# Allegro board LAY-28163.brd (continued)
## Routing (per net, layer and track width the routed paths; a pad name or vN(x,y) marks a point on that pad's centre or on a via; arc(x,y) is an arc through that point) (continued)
P3V3_K64F: length 34.4
  TOP w0.254: U14.40 54.33,12.98 C46.1 ; C49.1 57.42,10.41 U14.48
  TOP w0.305: C42.1 70.72,18.17 70.63,18.17 U14.75 ; U14.8 55.67,28.18 C25.1 ; U14.89 66.04,26.8 66.04,27.19 v1(66.33,27.48) ; U14.61 65.62,13.29 66.05,13.29 v1(66.07,13.27)
  TOP w0.33: v1(50.61,23.46) 50.61,23.34 U14.22
  TOP w0.381: C27.1 v1(66.33,27.48)
  TOP w0.508: C47.1 v1(67.39,12.41)
  TOP w0.635: 38.47,12.94 J20.2 39.42,13.89 ; v1(54.82,29.68) 55.18,29.68 C25.1 ; C49.1 57.01,9.99 v1(57.55,9.45) ; 42.42,13.76 R64.2 41.91,14.27 ; R52.1 v1(46.61,24.64) ; R66.2 41.75,13.88 ; R66.2 40.98,13.25 ; R66.2 40.22,13.88 ; C42.1 v1(72.12,17.57) ; C46.1 v1(52.74,12.06) ; R54.1 49.15,24.17 C37.1 50.61,23.75 v1(50.61,23.46)
  BOTTOM w0.635: 41.96,30.63 J9.1 ; J9.1 42.63,30.63 ; J9.1 42.63,31.3 ; J20.2 39.2,13.15 ; J20.2 38.47,12.94 ; J20.2 39.2,14.63 ; J20.2 39.42,13.89 ; 47.96,10.42 J23.2 47.75,9.68
  vias: v1(39.82,13.21) v1(39.83,12.04) v1(41.02,12.07) v1(41.56,13.1) v1(42.45,13.15) v1(42.48,12.12)
P3V3_SDA: length 48.2
  TOP w0.203: v1(42.56,42.75) 42.16,43.15 U3.1
  TOP w0.254: R4.2 v1(40.95,44.92) ; U2.1 46.72,43.77 v1(46.59,43.64) ; U5.7 19.63,39.65 19.32,39.34 19.32,38.97 19.09,38.73 18.74,38.73 C12.1 18.52,38.51 C15.1 ; v1(45.45,42.33) 45.88,41.91 U7.1 ; v1(36.39,35.29) U10.7 ; U5.11 v1(22.19,39.43) ; U9.5 v1(41.7,39.75) ; U12.1 v1(46.09,35.35)
  TOP w0.305: U5.1 v1(17.06,42.22)
  TOP w0.381: v1(36.39,35.29) 36.39,34.51 36.87,34.03 C17.1 ; J18.1 26.43,20.22 26.17,19.97 R61.2 ; v1(41.6,41.13) R14.1 ; R26.1 v1(40.64,39.36) ; v1(47.23,35.41) 47.64,34.99 R37.1 ; R23.1 v1(47.69,37.62)
  TOP w0.508: v1(42.97,39.01) 42.99,39.01 43.32,39.34 R27.2 ; v1(43.81,43.76) R12.1 ; R14.1 C8.1
  TOP w0.635: R17.1 v1(10.45,41.1) ; J10.1 27.32,31.3 C18.1 ; v1(20.26,36.77) C15.1 ; R21.1 v1(26.1,38.4) ; v1(15.19,42.15) C10.1 ; R35.1 v1(28.45,35.22)
  BOTTOM w0.635: J7.1 9.23,39.79 ; J7.1 8.28,38.83 ; J7.1 9.23,37.88 ; J10.1 27.02,31.3 ; 33.04,34.06 33.04,29.56 31.9,28.42 30.46,28.42 26.65,24.61 26.65,21.08 J18.1
P3V3_VREG: length 18.1
  TOP w0.762: 34.95,12.97 J19.2 34.22,13.18 ; C51.1 34.2,8.95 ; C51.1 34.2,7.42 ; C51.1 33.57,7.42 ; C51.1 33.57,8.18 ; 30.31,13.2 U17.2 29.61,13.2 ; 27.55,8.3 U17.4 ; U17.4 29.61,7 ; U17.4 29.61,9.59 ; U17.4 31.67,8.3 ; 34.28,9.95 D11.A ; D11.A 33.7,9.95 ; D11.A 33.64,10.84 ; D11.A 34.28,11.73
P5V0_SDA_USB_CONN_VBUS: length 5.8
  TOP w0.406: J26.1 5.21,43.49 6.51,44.79 U1.1
  TOP w0.762: U1.1 L1.1
P5V0_USB_CONN_VBUS: length 6
  TOP w0.406: U15.1 6.53,13.92 5.27,12.65 J22.1
  TOP w0.635: L5.1 8.84,14.59 8.16,13.92 U15.1
P5V_K64_USB: length 37.5
  TOP w0.508: J21.2 13.3,13.86 ; J21.2 13.3,11.95 ; J21.2 14.25,12.9 ; J21.2 12.35,12.9 ; C45.1 11.46,13.46 ; C45.1 10.95,12.95 ; C45.1 10.95,13.97 ; L5.2 10.24,15.72 ; L5.2 10.73,15.12 ; L5.2 10.24,14.52 ; 19.01,11.97 D8.A ; D8.A 18.12,12.62 ; D8.A 19.9,12.62 ; 15.3,12.62 D7.A ; D7.A 16.19,13.27 ; D7.A 16.19,11.97 ; D7.A 17.08,12.62
  BOTTOM w0.762: J16.2 40.24,19.65 37.63,19.65 35.93,17.95 33.94,17.95 29.76,13.76 21.38,13.76 v2(18.97,11.36)
P5V_OPT_VR: length 4.5
  TOP w0.762: J27.3 4.49,4.52 4.88,4.9 C53.1
  TOP w0.889: C53.1 D13.A
P5V_SDA: length 68.3
  TOP w0.127: v1(18.81,39.35) 18.8,39.36 18.8,39.54 U5.6
  TOP w0.381: R5.1 v1(23.71,45.86)
  TOP w0.508: v2(29.35,39.98) 29.35,39.22 30.97,37.6 35.03,37.6 35.63,37.01 R34.1 35.6,35.87 34.67,34.94 C16.1 ; C16.1 34.67,32.58 C19.1 ; C16.1 33.29,34.33 U11.1 ; R8.1 v1(17.91,45.84)
  TOP w0.635: v2(12.2,46.18) 12.1,46.18 12.09,46.19 C1.1 L1.2
  BOTTOM w0.381: v1(23.71,45.86) 23.13,46.44 19.09,46.44 18.48,45.84 v1(17.91,45.84)
  BOTTOM w0.508: v1(17.91,45.84) 17.28,45.84 16.28,44.84 13.54,44.84 v2(12.2,46.18) ; v1(23.71,45.86) 24.91,44.66 28.25,44.66 29.8,43.11 29.8,41.2 29.35,40.75 v2(29.35,39.98)
  BOTTOM w0.762: v1(18.81,39.35) 18.81,37.39 17.8,36.38 13.87,36.38 13.33,36.92 8.25,36.92 7.38,37.79 7.38,42.26 11.31,46.18 v2(12.2,46.18)
P5V_SDA_PSW: length 23.2
  TOP w0.635: U11.6 v2(29.61,34.34)
  TOP w0.762: D6.A 21.74,20.49 v2(20.39,20.49) D5.A
  BOTTOM w0.635: v2(29.61,34.34) 29.61,32.3 27.43,30.12 24.69,30.12 20.39,25.82 v2(20.39,20.49)
P5V_USB: length 53.3
  TOP w1.016: D5.C 17.01,17.94 v2(16.19,17.12) D7.C 14.93,15.17 14.65,15.44 J21.1 ; D13.C v2(8.76,7.28)
  INT_1 w1.016: v2(15.86,6.86) 16.49,6.23 16.98,6.23 19.69,3.53 22.53,3.53 25.14,0.93 36.94,0.93 38.06,2.05 J3.10
  BOTTOM w1.016: v2(8.76,7.28) 9.65,7.28 10.07,6.86 v2(15.86,6.86) 16.82,7.82 16.82,16.49 v2(16.19,17.12)
VBAT: length 6.7
  TOP w0.254: C43.1 51.06,15.06 51.06,16.77 U14.30
  TOP w0.635: J23.1 50.5,14.35 C43.1
VDDA_ENET: length 18.8
  TOP w0.254: C24.1 32.38,29.47 U13.2
  TOP w0.508: L3.2 30.29,31.08 30.29,30.25 v1(30.15,30.11) ; L3.2 31.66,31.09 C21.1 32.87,31.09 C22.1 C24.1 ; L3.2 R42.2 ; v1(21.76,32.28) 20.78,32.28 R41.1
  INT_1 w0.254: v1(30.15,30.11) 29.29,30.97 28.11,30.97 27.35,30.2 23.84,30.2 v1(21.76,32.28)
VDDIO_ENET: length 70.1
  TOP w0.279: U13.14 30.88,23.72 C39.1 30.88,21.27 30.88,21.27 J17.1
  TOP w0.381: D3.1 v1(40.72,26.92)
  TOP w0.635: J17.1 29.67,20.24 28.78,21.13 R55.1 28.77,22.63 R56.1 ; v1(38.17,24.86) 38.17,25.35 R50.1 ; R60.2 v1(33.3,21.3) ; R76.1 v1(11.05,16.7)
  BOTTOM w0.635: J13.13 2.73,26.93 5.57,24.09 8.02,24.09 11.05,21.06 v1(11.05,16.7) 11.75,16.7 13.2,18.15 18.06,18.15 19.99,16.22 28.41,16.22 29.04,16.86 29.04,18.4 J17.1 31.94,21.3 v1(33.3,21.3) 35.52,21.3 38.17,23.94 v1(38.17,24.86) 38.17,26.36 38.73,26.92 v1(40.72,26.92)
VDDPLL_1.2V: length 3.2
  TOP w0.114: U13.1 34.42,28.34 C26.1 36.08,28.34 C28.1
ADC0_DM0/ADC1_DM3: length 45.7
  TOP w0.114: v1(51.23,24.6) 51.64,24.6 51.73,24.51 51.73,24.35 U14.19
  INT_1 w0.119: J2.7 35.11,48.29 35.23,48.17 35.23,47.38 37.12,45.49 37.12,41.16 39.72,38.56 39.72,36.24 39.38,35.9 39.38,30.26 40.98,28.65 49.36,28.65 51.71,31 52.8,31 53.3,30.5 53.3,28.18 50.98,25.85 50.98,25.24 51.23,24.99 v1(51.23,24.6)
ADC0_DM1: length 30.5
  TOP w0.114: v1(56.74,23.83) 55.08,23.83 U14.15
  INT_1 w0.13: v1(56.74,23.83) 56.74,18.69 62.49,12.94 62.49,10.2 58.94,6.65 54.91,6.65 J4.3
ADC0_DP0/AD1_DP3: length 45.4
  TOP w0.114: v1(51.83,25.2) 51.83,24.81 51.94,24.7 52.08,24.7 U14.18
  INT_1 w0.119: J2.5 35.65,48.29 35.53,48.17 35.53,47.51 37.42,45.62 37.42,41.28 40.02,38.69 40.02,36.12 39.67,35.78 39.67,30.38 41.11,28.95 49.24,28.95 51.59,31.3 52.92,31.3 53.6,30.62 53.6,28.05 51.27,25.73 51.27,25.37 51.44,25.2 v1(51.83,25.2)
ADC0_DP1: length 31.9
  TOP w0.114: 54.3,25.31 55.2,24.41 v1(56.15,24.41)
  INT_1 w0.13: v1(56.15,24.41) 56.15,18.62 61.92,12.85 61.92,10.43 58.55,7.06 52.78,7.06 J4.1
ADC1_DM0/ADC0_DM3: length 52
  TOP w0.114: v1(43.52,22.07) 43.93,22.07 44.05,22.2 44.05,24.2 42.68,25.58 42.68,26.54 42.6,26.63 v1(42.19,26.63) ; v1(47.26,20.98) 47.55,20.69 48.61,20.69 49,20.3 51.18,20.3 52.64,21.76 52.64,22.02 U14.21
  INT_1 w0.119: v1(47.26,20.98) 46.98,20.7 46.79,20.7 44.96,22.52 44.36,22.52 44.19,22.35 43.8,22.35 v1(43.52,22.07) ; J2.13 27.58,48.29 28.61,47.26 29.99,47.26 30.06,47.32 30.56,47.32 31.21,46.67 32.84,46.67 34.53,44.98 34.53,43.19 36.14,41.59 36.14,40.34 38.2,38.27 38.2,34.66 38.2,32.72 37.7,32.22 37.7,28.03 38.37,27.36 41.85,27.36 42.19,27.02 v1(42.19,26.63)
ADC1_DM1: length 28.1
  TOP w0.114: v1(58.18,22.76) 54.73,22.76 U14.17
  INT_1 w0.13: J4.7 59.49,5.12 63.55,9.18 63.55,13.24 58.18,18.61 v1(58.18,22.76)
ADC1_DP0/ADC0_DP3: length 51.8
  TOP w0.114: U14.20 52.92,22.45 52.92,21.65 51.3,20.03 48.88,20.03 48.5,20.41 47.55,20.41 v1(47.26,20.12) ; v1(44.12,21.46) 44.12,21.88 44.33,22.08 44.33,24.32 44,24.65 44,24.79 44.17,24.96 44.17,25.1 44.07,25.2 43.92,25.2 43.75,25.03 43.61,25.03 43.51,25.13 43.51,25.28 43.68,25.45 43.68,25.59 43.58,25.69 43.44,25.69 43.27,25.52 43.13,25.52 42.96,25.69 42.96,26.66 42.8,26.82 v1(42.8,27.24)
  INT_1 w0.119: v1(42.8,27.24) 42.4,27.24 41.97,27.66 38.49,27.66 38,28.15 38,32.09 38.5,32.59 38.5,34.17 38.5,34.17 38.5,34.79 38.5,34.79 38.5,38.4 36.43,40.46 36.43,41.76 34.83,43.36 34.83,45.1 32.96,46.97 31.33,46.97 30.68,47.62 30.35,47.62 29.68,48.29 J2.11 ; v1(47.26,20.12) 46.98,20.4 46.67,20.4 44.84,22.23 44.49,22.23 44.4,22.14 44.4,21.75 v1(44.12,21.46)
ADC1_DP1: length 29.1
  TOP w0.114: U14.16 54.91,23.29 v1(57.39,23.29)
  INT_1 w0.13: v1(57.39,23.29) 57.39,18.64 63.02,13 63.02,9.93 59.34,6.25 57.05,6.25 J4.5
ADC1_SE18: length 51.6
  TOP w0.114: v1(39.1,26.22) 39.41,25.91 39.42,25.91 41.41,23.91 v1(41.41,21.33) ; v1(48.51,19.67) 48.94,19.24 50.11,19.24 U14.26
  INT_1 w0.13: v1(39.1,26.22) 38.64,26.22 36.55,28.3 36.55,30.1 37.24,30.79 37.24,38.57 35.78,40.03 35.78,41.45 34.54,42.69 33.25,42.69 32.57,43.37 32.57,45.35 31.74,46.17 30.69,46.17 29.86,47 22.7,47 J2.17 ; v1(48.51,19.67) 46.84,19.67 45.62,20.9 41.84,20.9 v1(41.41,21.33)
AREF: length 42.7
  TOP w0.114: R53.2 45.96,25.12 45.96,25.25 45.29,25.92 45.29,27.55 v1(44.71,28.14)
  INT_1 w0.13: v1(44.71,28.14) 43.24,28.14 43.03,28.34 40.1,28.34 39.04,29.41 39.04,36.15 39.43,36.54 39.43,38.2 36.78,40.85 36.78,41.96 35.16,43.58 35.16,45.5 32.96,47.7 32.96,48.66 32.09,49.53 25.25,49.53 J2.16
CPU_PER_1_RST_B: length 6.9
  TOP w0.114: J14.1 43,24.49 41.74,25.75 R47.1 R45.2
CRS_DV: length 6.3
  TOP w0.114: RN1.1 35.47,22.08 35.47,22.08 v1(34.92,22.08) ; U13.15 31.38,23.61 v1(31.54,23.44)
  INT_1 w0.13: v1(34.92,22.08) 33.56,23.44 v1(31.54,23.44)
DAC0_OUT: length 28.5
  TOP w0.114: U14.27 54.09,21.93 v1(58.67,21.93)
  INT_1 w0.13: v1(58.67,21.93) 58.67,18.66 64.04,13.29 64.04,8.13 63.54,7.64 J4.11
DC_JACK: length 2.9
  TOP w1.016: J24.1 21.39,11.12 21.76,11.49 21.76,11.52 21.77,11.52 D9.A
ENET1_CT: length 19
  TOP w0.508: v1(17.75,33.3) C20.1 R41.2
  INT_1 w0.508: v1(17.75,33.3) 12.17,33.3 11.13,32.26 11.13,30.03 J13.3
  BOTTOM w0.127: J13.6 13.62,26.27 13.62,27.54 J13.3
ENET1_RX+: length 25.9
  TOP w0.089: v1(22.34,23.62) 22.08,23.36 19.73,23.36 19.07,24.02 R51.1 18.48,24.14 18.39,24.05 18.39,23.47 18.3,23.38 16.98,23.38 16.67,23.7 13.99,23.7 13.37,23.08 13,23.08 J13.7 ; U13.4 31.38,28.84 31.5,28.96 31.5,29.57 v1(31.22,29.86)
  INT_1 w0.089: v1(31.22,29.86) 31.45,29.62 31.45,28.91 31.17,28.63 30.59,28.63 25.33,23.37 22.6,23.37 v1(22.34,23.62)
ENET1_RX-: length 26.5
  TOP w0.089: v1(22.34,22.8) 22.04,23.11 19.73,23.11 19.07,22.45 R59.1 18.48,22.36 18.39,22.45 18.39,23.04 18.3,23.12 16.88,23.12 16.56,23.44 14.1,23.44 13.81,23.16 13.81,22.59 14.03,22.36 J13.8 ; U13.3 31.88,28.84 31.76,28.96 31.76,29.57 v1(32.04,29.86)
  INT_1 w0.089: v1(32.04,29.86) 31.71,29.53 31.71,28.8 31.28,28.37 30.7,28.37 25.44,23.11 22.65,23.11 v1(22.34,22.8)
ENET1_TX+: length 22.3
  TOP w0.089: J13.1 13.52,30.71 13.56,30.6 13.45,30.44 13.45,29.08 14,28.52 17.2,28.52 17.87,29.19 18.24,29.19 18.33,29.1 18.33,28.53 18.42,28.44 R48.1 19.01,28.5 19.7,29.2 21.63,29.2 22.01,29.59 28.14,29.59 28.4,29.33 29.98,29.33 30.38,28.93 U13.6
ENET1_TX-: length 22.3
  TOP w0.089: J13.2 13.91,30.52 13.79,30.48 13.7,30.36 13.7,29.18 14.11,28.78 17.09,28.78 17.76,29.45 18.24,29.45 18.33,29.54 18.33,30.11 18.42,30.2 R44.1 19.01,30.14 19.7,29.45 21.52,29.45 21.91,29.84 28.25,29.84 28.5,29.58 30.09,29.58 30.88,28.79 U13.5
ENET_1_RX_RDIV: length 5.3
  TOP w0.114: C36.1 20.59,25.14 20.59,25.13 R51.2 v1(21.48,24.14) ; v1(21.48,22.16) 21.28,22.36 R59.2
  INT_1 w0.13: v1(21.48,24.14) 21.48,22.62 21.48,22.61 v1(21.48,22.16)
ENET_1_TX_RDIV: length 5.1
  TOP w0.114: C31.1 20.53,27.68 20.53,27.69 R48.2 20.54,28.45 v1(21.5,28.45) ; R44.2 v1(21.5,30.2)
  INT_1 w0.13: v1(21.5,30.2) v1(21.5,28.45)
EXTAL32_RTC: length 2.6
  TOP w0.114: U14.29 50.63,17.05 50.63,16.27 R63.1
EXTAL_32.768KHZ: length 5.2
  TOP w0.114: Y3.2 47.38,12.28 47.81,12.28 C48.1 48.52,12.99 48.52,13.47 48.49,13.5 48.49,14.13 49.13,14.77 R63.2
FXOS8700CQ_CRST: length 3.7
  TOP w0.114: v1(52.26,38.29) 51.82,37.85 C13.1
  TOP w0.127: v1(52.26,38.29) 52.7,38.29 52.79,38.38 U8.8
FXOS8700CQ_I2C_SA0: length 7.1
  TOP w0.114: v1(51.24,38.88) 50.83,38.88 50.79,38.92 TP8.1 R32.2 R31.1
  TOP w0.127: U8.7 v1(51.24,38.88)
FXOS8700CQ_I2C_SA1: length 7.8
  TOP w0.114: R40.2 R43.1 57.09,32.17 TP11.1 56.16,33.11 56.16,33.41 v1(55.82,33.74)
  TOP w0.127: v1(55.82,33.74) 55.82,34.63 55.82,34.63 55.82,35 55.82,35.01 U8.10
I2S_MCLK: length 8.6
  TOP w0.114: J1.7 57.16,47.02 61.14,47.02 62.77,45.39 R79.1
K64_MICRO_USB_DN: length 2.7
  TOP w0.114: U14.11 54.56,27.17 54.56,27.33 54.48,27.41 54.47,27.41 54.14,27.75 R49.2
K64_MICRO_USB_DP: length 2.7
  TOP w0.114: R46.2 54.33,27.95 54.59,27.69 54.59,27.69 54.75,27.53 54.91,27.53 U14.10
LED1/SPEED: length 18.8
  TOP w0.114: v1(34.37,27.13) 34.37,27.13 U13.23 ; v1(22.54,34.11) R36.1
  INT_1 w0.13: v1(34.37,27.13) 34.37,27.63 32.92,29.08 32.92,29.75 32.02,30.65 31.99,30.65 31.14,31.5 27.9,31.5 27.02,30.62 24.72,30.62 22.54,32.8 v1(22.54,34.11)
LED2_LINK: length 7.8
  TOP w0.635: R76.2 7.98,16.7 v1(7.93,16.75)
  BOTTOM w0.635: v1(7.93,16.75) 6.7,16.75 3.78,19.67 3.53,19.67 J13.11
LEDRGB_BLUE: length 5.7
  TOP w0.114: R71.1 v1(73.43,10.26) TP14.1 76.3,10.26 76.85,9.71 D12.3
LEDRGB_GREEN: length 7.6
  TOP w0.114: R73.1 v1(73.47,8.77) TP17.1 75.62,7.54 78.05,7.54 78.35,7.84 D12.4
LEDRGB_RED: length 7.5
  TOP w0.114: D12.1 78.35,12.71 78.07,12.99 75.57,12.99 TP13.1 v1(73.39,11.81) R68.2
LVLRST_EN: length 1.1
  TOP w0.114: R4.1 41.97,45.25 41.98,45.24 U3.5
MIC2005_CSLEW: length 4.2
  TOP w0.114: U11.5 31.58,35.29 32.17,34.7 32.17,33.56 C19.2
MMA8451_BYP: length 6
  TOP w0.114: C3.1 56.09,45.02 56.26,44.85 TP4.1 v1(56.82,43.99)
  TOP w0.127: U8.2 56.82,42.72 56.83,42.73 56.83,43.14 56.82,43.14 56.82,43.32 56.82,43.52 56.82,43.52 v1(56.82,43.99)
NC1: length 3.1
  TOP w0.114: J13.4 13.72,26.17 J13.5
Net_211: length 3.5
  TOP w0.127: 57.6,38.88 v1(61.06,38.88)
P5-9V_VIN: length 54
  TOP w0.889: J27.1 10.69,4.05 10.69,4.82 10.67,4.84 C54.1 C52.1 C50.1 v1(10.67,10.51)
  TOP w1.016: D10.A v2(24.67,11.2)
  INT_1 w0.889: v2(24.67,11.2) 23.05,12.82 18.63,12.82 16.21,10.4 10.78,10.4 v1(10.67,10.51)
  BOTTOM w0.889: J3.16 47.31,4.21 47.31,5.81 45.63,7.5 28.37,7.5 v2(24.67,11.2)
P5-9V_VIN_VR: length 17.3
  TOP w0.508: C41.1 24.74,17.34 ; C41.1 23.21,17.34 ; C41.1 23.97,16.71 ; D9.C 22.66,15.17 ; D9.C 21.77,13.87 ; D9.C 20.88,15.17 ; 22.64,17.93 D6.C 20.86,17.93 ; 27.31,13.2 U17.3 ; U17.3 28.1,14.5 ; U17.3 26.52,14.5 ; 23.78,15.17 D10.C ; D10.C 24.67,16.46 ; D10.C 25.56,15.17 ; D10.C 24.67,13.87 ; 19.01,13.87 D8.C ; D8.C 19.9,15.17 ; D8.C 18.12,15.17
  vias: v1(25.97,14.85)
PHY_RST_B: length 1.2
  TOP w0.114: D3.2 40.72,27.97 40.73,27.98 40.73,28.78
POWER_EN: length 16
  TOP w0.114: R29.1 27.79,39.2 27.27,38.68 v1(27.27,37.98) ; 17.86,43.05 v1(16.94,43.97)
  INT_1 w0.13: v1(27.27,37.98) 26.29,38.96 21.95,38.96 v1(16.94,43.97)
PTA0: length 40.8
  TOP w0.114: v1(54.81,17.7) U14.34 ; v1(49.08,24.99) 49.08,29.24 48.91,29.41 J11.1
  INT_1 w0.13: v1(49.08,24.99) 49.08,24.55 50.14,23.48 50.14,22.36 v1(54.81,17.7) ; J2.2 42.81,49.74 42.81,46.78 47.13,42.47 47.13,36.29 47.82,35.6 47.82,32.86 48.91,31.77 J11.1
PTA1: length 42.1
  TOP w0.114: v1(60.43,21.24) 59.64,20.45 58.27,20.45 U14.35
  INT_1 w0.13: v1(60.43,21.24) 60.43,22.32 57.97,24.78 57.97,32.42 58.5,32.95 58.5,43.9 54.62,47.78 54.62,49.54 J1.8
PTA2: length 41.7
  TOP w0.114: R80.2 54.17,31.58 v1(54.18,31.59) ; U14.36 v1(55.98,17.45)
  INT_1 w0.13: v1(55.98,17.45) 54.96,18.48 54.96,19.55 54.61,19.91 54.61,27.62 55.32,28.33 55.32,30.46 v1(54.18,31.59) 55.12,32.53 55.12,33.61 54.83,33.91 54.83,41.9 49.55,47.18 49.55,49.55 J1.12
PTA3: length 24.8
  TOP w0.114: J9.2 41.55,30.44 42.37,30.44 44.01,28.8 J12.2 44.01,26.06 45.01,25.06 v1(45.01,23.51) ; 54.3,15.06 v1(55.28,16.04)
  INT_1 w0.13: v1(55.28,16.04) 52.98,16.04 45.51,23.51 v1(45.01,23.51)
PTA4: length 34.4
  TOP w0.114: v1(66.63,10.01) 69.22,7.43 C55.1 R75.2 72.79,4.53 72.8,4.53 SW3.1 ; U14.38 59.43,19.48 v1(59.88,19.48)
  INT_1 w0.13: v1(66.63,10.01) 68.7,12.08 68.7,13.69 67.63,14.77 63.91,14.77 59.88,18.8 v1(59.88,19.48)
PTA5: length 39
  TOP w0.114: RN1.7 v1(38.76,21.21) ; v1(55.89,15.24) U14.39
  INT_1 w0.13: v1(38.76,21.21) 39.39,20.58 39.39,19.47 40,18.86 43.91,18.86 44.02,18.98 44.02,20.2 44.14,20.31 44.3,20.31 44.41,20.2 44.41,18.97 44.53,18.85 44.69,18.85 44.8,18.97 44.8,20.2 44.92,20.31 45.08,20.31 45.19,20.2 45.19,19.03 45.3,18.92 46.69,18.92 46.8,19.03 46.8,19.14 46.92,19.26 47.08,19.26 47.19,19.14 47.19,19.03 47.31,18.92 47.47,18.92 47.58,19.03 47.58,19.14 47.69,19.26 47.86,19.26 47.97,19.14 47.97,19.03 48.08,18.92 48.87,18.92 49.05,18.74 49.05,18.58 48.5,18.03 48.5,17.87 48.62,17.75 48.78,17.75 49.33,18.3 49.49,18.3 49.8,17.99 49.8,17.83 49.28,17.31 49.28,17.15 49.39,17.04 49.55,17.04 50.07,17.56 50.23,17.56 50.87,16.92 50.87,16.76 50.36,16.25 50.36,16.09 50.47,15.97 50.63,15.97 51.15,16.48 51.31,16.48 51.42,16.37 51.42,16.21 50.91,15.7 50.91,15.54 51.02,15.42 51.18,15.42 51.7,15.94 51.86,15.94 52.23,15.56 52.95,15.56 53.07,15.45 53.07,14.9 53.18,14.79 53.34,14.79 53.45,14.9 53.45,15.45 53.57,15.56 53.73,15.56 53.84,15.45 53.84,14.9 53.96,14.79 54.12,14.79 54.23,14.9 54.23,15.45 54.35,15.56 54.51,15.56 54.62,15.45 54.62,14.9 54.73,14.79 54.9,14.79 55.01,14.9 55.01,15.45 55.12,15.56 55.58,15.56 v1(55.89,15.24)
PTA12: length 40.4
  TOP w0.114: v1(57.52,14.95) 57.21,14.64 57.21,14.45 56.98,14.22 56.98,14.21 55.24,12.47 54.6,12.47 ; v1(38.76,20.41) RN1.6
  INT_1 w0.13: v1(57.52,14.95) 57.21,14.64 57.21,14.45 56.68,13.92 56.17,13.92 56.06,14.03 56.06,14.31 55.94,14.42 55.78,14.42 55.67,14.31 55.67,14.03 55.55,13.92 55.39,13.92 55.28,14.03 55.28,14.31 55.16,14.42 55,14.42 54.89,14.31 54.89,14.03 54.78,13.92 54.61,13.92 54.5,14.03 54.5,14.31 54.39,14.42 54.23,14.42 54.11,14.31 54.11,14.03 54,13.92 53.84,13.92 53.72,14.03 53.72,14.31 53.61,14.42 53.45,14.42 53.33,14.31 53.33,14.03 53.22,13.92 53.06,13.92 52.95,14.03 52.95,14.31 52.83,14.42 52.67,14.42 52.56,14.31 52.56,14.03 52.44,13.92 51.78,13.92 51.14,14.55 50.98,14.55 50.69,14.26 50.53,14.26 50.42,14.38 50.42,14.54 50.71,14.82 50.71,14.99 50.59,15.1 50.43,15.1 50.14,14.81 49.98,14.81 49.87,14.93 49.87,15.09 50.16,15.37 50.16,15.54 50.04,15.65 49.88,15.65 49.59,15.36 49.43,15.36 49.32,15.48 49.32,15.64 49.61,15.92 49.61,16.09 49.49,16.2 49.33,16.2 49.04,15.91 48.88,15.91 48.77,16.03 48.77,16.19 49.06,16.47 49.06,16.63 48.94,16.75 48.78,16.75 48.49,16.46 48.33,16.46 48.22,16.58 48.22,16.74 48.51,17.02 48.51,17.18 48.39,17.3 48.23,17.3 47.95,17.01 47.78,17.01 47.67,17.12 47.67,17.29 47.96,17.57 47.96,17.73 47.84,17.85 47.68,17.85 47.4,17.56 47.23,17.56 47.12,17.67 47.12,17.84 47.41,18.12 47.41,18.28 47.23,18.47 41.72,18.47 41.6,18.35 41.6,17.89 41.49,17.77 41.33,17.77 41.22,17.89 41.22,18.35 41.1,18.47 40.94,18.47 40.83,18.35 40.83,17.89 40.71,17.77 40.55,17.77 40.44,17.89 40.44,18.35 40.32,18.47 39.93,18.47 38.76,19.64 v1(38.76,20.41)
PTA13: length 39.3
  TOP w0.114: R69.1 55.7,12.19 55.7,12.23 U14.43 57.31,13.83 v1(57.31,13.85) ; RN1.5 38.5,19.55 38.97,19.08 38.97,18.76 v1(39.28,18.45)
  INT_1 w0.13: v1(39.28,18.45) 40.28,17.45 42.03,17.45 42.15,17.57 42.15,17.98 42.26,18.1 42.42,18.1 42.54,17.98 42.54,17.57 42.65,17.45 42.81,17.45 42.92,17.57 42.92,17.98 43.04,18.1 43.2,18.1 43.31,17.98 43.31,17.57 43.43,17.45 43.59,17.45 43.7,17.57 43.7,17.98 43.82,18.1 43.98,18.1 44.09,17.98 44.09,17.57 44.2,17.45 44.37,17.45 44.48,17.57 44.48,17.98 44.59,18.1 44.75,18.1 44.87,17.98 44.87,17.57 44.98,17.45 45.14,17.45 45.26,17.57 45.26,17.98 45.37,18.1 45.53,18.1 45.65,17.98 45.65,17.57 45.76,17.45 45.92,17.45 46.03,17.57 46.03,17.98 46.15,18.1 46.31,18.1 46.42,17.98 46.42,17.67 46.65,17.45 46.65,17.29 46.24,16.88 46.24,16.71 46.35,16.6 46.51,16.6 46.92,17.01 47.08,17.01 47.2,16.9 47.2,16.74 46.79,16.33 46.79,16.17 46.9,16.05 47.06,16.05 47.47,16.46 47.63,16.46 47.75,16.35 47.75,16.19 47.34,15.78 47.34,15.62 47.45,15.5 47.61,15.5 48.02,15.91 48.18,15.91 48.3,15.8 48.3,15.64 47.89,15.23 47.89,15.07 48,14.95 48.16,14.95 48.57,15.36 48.73,15.36 48.85,15.25 48.85,15.09 48.44,14.68 48.44,14.52 48.55,14.4 48.71,14.4 49.12,14.81 49.28,14.81 49.4,14.7 49.4,14.54 48.99,14.13 48.99,13.97 49.1,13.85 49.26,13.85 49.67,14.26 49.83,14.26 50.56,13.53 56.99,13.53 v1(57.31,13.85)
PTA14: length 38.9
  TOP w0.114: v1(58.31,14.13) 58,13.82 58,13.82 57.75,13.57 57.75,13.56 U14.44 55.95,11.76 R70.1 ; RN1.8 38.62,22.08 39.46,21.24 39.46,19.24 39.91,18.79 39.91,17.95 v1(40.85,17.01)
  INT_1 w0.13: v1(58.31,14.13) 57.21,13.03 50.21,13.03 50.1,13.15 50.1,13.4 49.98,13.51 49.82,13.51 49.71,13.4 49.71,13.15 49.59,13.03 49.17,13.03 48.86,13.34 48.7,13.34 48.3,12.95 48.14,12.95 48.03,13.06 48.03,13.23 48.42,13.62 48.42,13.78 48.31,13.89 48.15,13.89 47.75,13.5 47.59,13.5 47.48,13.61 47.48,13.77 47.87,14.17 47.87,14.33 47.76,14.44 47.6,14.44 47.2,14.05 47.04,14.05 46.93,14.16 46.93,14.32 47.32,14.72 47.32,14.88 47.21,14.99 47.05,14.99 46.65,14.6 46.49,14.6 46.38,14.71 46.38,14.87 46.77,15.27 46.77,15.43 46.66,15.54 46.5,15.54 46.1,15.15 45.94,15.15 45.83,15.26 45.83,15.42 46.22,15.82 46.22,15.98 46.11,16.09 45.95,16.09 45.55,15.7 45.39,15.7 45.28,15.81 45.28,15.97 45.67,16.37 45.67,16.53 45.2,17.01 v1(40.85,17.01)
PTA15: length 40.2
  TOP w0.114: v1(37.04,24.21) 36.69,23.86 34.44,23.86 33.58,24.72 U13.19 ; v1(58.02,13.13) U14.45
  INT_1 w0.13: v1(37.04,24.21) 37.04,23.68 36.73,23.37 36.73,20.36 40.61,16.48 42.26,16.48 42.37,16.37 42.37,15.3 42.49,15.19 42.65,15.19 42.76,15.3 42.76,16.37 42.87,16.48 43.04,16.48 43.15,16.37 43.15,15.3 43.26,15.19 43.42,15.19 43.54,15.3 43.54,16.37 43.65,16.48 43.92,16.48 47.87,12.53 48.54,12.53 48.65,12.42 48.65,11.95 48.77,11.84 48.93,11.84 49.04,11.95 49.04,12.42 49.15,12.53 57.1,12.53 57.43,12.53 v1(58.02,13.13)
PTA16: length 41.7
  TOP w0.114: U14.46 59.16,13.56 59.16,13.91 v1(59.47,14.22) ; v1(35.23,24.45) 34.63,24.45 34.39,24.69 34.39,25.37 34.12,25.63 U13.20
  INT_1 w0.13: v1(59.47,14.22) 59.16,13.91 59.16,13.58 58.39,12.82 58.39,12.79 57.29,11.69 56.94,11.69 56.83,11.58 56.83,11.35 56.72,11.23 56.55,11.23 56.44,11.35 56.44,11.58 56.33,11.69 56.17,11.69 56.05,11.58 56.05,11.35 55.94,11.23 55.78,11.23 55.66,11.35 55.66,11.58 55.55,11.69 55.39,11.69 55.28,11.58 55.28,11.35 55.16,11.23 55,11.23 54.89,11.35 54.89,11.58 54.77,11.69 54.52,11.69 53.3,10.47 52.43,10.47 52.32,10.59 52.32,10.73 52.21,10.84 52.05,10.84 51.93,10.73 51.93,10.59 51.82,10.47 49.99,10.47 49.18,11.29 48.4,11.29 44.98,14.71 41.81,14.71 36.28,20.24 36.28,22.22 35.23,23.27 v1(35.23,24.45)
PTA17: length 39.5
  TOP w0.114: v1(34.99,25.11) 34.99,25.55 34.41,26.13 U13.21 ; v1(58.74,12.44) U14.47
  INT_1 w0.13: v1(58.74,12.44) 57.02,10.71 54.94,10.71 54.09,9.86 49.87,9.86 48.98,10.75 47.73,10.75 47.1,10.12 46.11,10.12 42.27,13.96 40.44,13.96 39.34,15.06 37.97,15.06 37.41,15.62 37.41,18.31 35.59,20.13 35.59,22.29 34.55,23.33 34.55,24.68 v1(34.99,25.11)
PTB0: length 51.8
  TOP w0.114: U13.10 29.13,26.13 27.28,24.29 R56.2 27.94,23.64 27.95,23.64 v1(28.08,23.64) ; v1(61.18,12.05) 61.19,12.05 61.19,12.05 61.2,12.05 U14.53
  INT_1 w0.13: v1(61.18,12.05) 61.18,11.01 57.78,7.61 41.65,7.61 36.21,13.06 36.21,17.11 35.7,17.63 33.26,17.63 31.6,19.28 30.11,19.28 28.08,21.31 v1(28.08,23.64)
PTB1: length 49.1
  TOP w0.114: U13.11 29.13,25.63 28.78,25.28 R55.2 v1(29.54,23.66) ; v1(60.73,13.11) 61.04,12.8 61.15,12.8 U14.54
  INT_1 w0.13: v1(29.54,23.66) 29.54,23.01 34.32,18.23 35.66,18.23 36.63,17.26 36.63,13.52 42.05,8.1 57.45,8.1 60.73,11.37 v1(60.73,13.11)
PTB2: length 19.9
  TOP w0.114: U14.55 63.76,10.9 63.76,8.9 61.82,6.96 53.59,6.96 52.15,5.52 52.15,3.89 J4.2
PTB3: length 18.5
  TOP w0.114: J4.4 54.59,3.79 54.59,5.63 55.35,6.39 62.18,6.39 64.11,8.31 64.11,11.26 U14.56
PTB9: length 41.8
  TOP w0.114: v1(62.57,17.28) 62.57,13.5 U14.57
  INT_1 w0.13: v1(62.57,17.28) 61.46,18.39 61.46,21.88 58.38,24.96 58.38,31.69 58.93,32.25 58.93,45.9 57.18,47.64 57.18,49.56 J1.6
PTB10: length 16.9
  TOP w0.114: J4.6 57.14,3.8 61.63,3.8 62.25,4.42 62.25,5.62 64.56,7.93 64.56,12.23 U14.58
PTB11: length 19.1
  TOP w0.114: J4.8 59.7,1.34 64.27,1.34 65.17,2.24 65.17,12.32 U14.59
PTB16: length 43.5
  TOP w0.114: U14.62 63.43,16.18 63.43,17.44 62.86,18.01 60.07,18.01 v1(57.95,15.89) ; R24.2 46.68,37.44 48.86,35.25 48.86,33.03 48.53,32.7 46.15,32.7 45.25,31.8 45.25,30.13 48.41,26.96 v1(48.41,24.1)
  INT_1 w0.13: v1(57.95,15.89) 56.87,16.97 54.33,16.97 48.41,22.89 v1(48.41,24.1)
PTB17: length 40.9
  TOP w0.114: v1(41.48,24.89) 41.04,24.89 39.83,26.1 39.83,27.81 39.47,28.18 39.47,31.79 R38.2 ; v1(56.85,15.88) 59.5,18.52 63.07,18.52 64.05,17.54 64.05,16.27 U14.63
  INT_1 w0.13: v1(41.48,24.89) 45.15,24.89 49.36,20.67 49.36,20.64 49.62,20.38 49.66,20.38 53.5,16.54 56.2,16.54 v1(56.85,15.88)
PTB18: length 35.4
  TOP w0.114: U14.64 64.66,16.37 v1(64.66,17.6)
  INT_1 w0.13: J1.1 63.53,46.97 64.27,46.23 64.27,28.85 66.06,27.06 66.06,21.1 64.97,20.01 64.97,17.91 v1(64.66,17.6)
PTB19: length 35.1
  TOP w0.114: U14.65 65.11,16.62 65.11,17.82 v1(64.49,18.45)
  INT_1 w0.13: J1.3 60.99,46.76 63.01,44.73 63.01,28.46 64.49,26.98 v1(64.49,18.45)
PTB20: length 17.5
  TOP w0.114: U14.66 67.39,15.05 67.39,14.77 68.23,13.92 v1(68.23,13.37)
  INT_1 w0.13: J4.9 62.07,4.05 63.92,4.05 64.86,4.98 64.86,8.87 68.23,12.25 v1(68.23,13.37)
PTB21: length 8.2
  TOP w0.114: R71.2 70.35,10.26 68.68,11.92 68.68,13.9 67.74,14.85 67.74,15.41 U14.67
PTB22: length 6.7
  TOP w0.114: R68.1 70.68,11.81 69.12,13.37 69.12,13.92 68.01,15.03 68.01,15.84 U14.68
PTB23: length 54.8
  TOP w0.114: v1(65.58,19.71) 66.89,18.4 66.89,17.68 U14.69
  INT_1 w0.13: v1(65.58,19.71) 68.07,22.2 68.07,24.63 68.44,24.99 68.44,26.73 70.86,29.15 70.86,40.89 70.34,41.41 66.75,41.41 65.32,42.83 65.32,47.57 65.05,47.85 65.05,51.43 64.22,52.26 54.8,52.26 J1.10
PTC0: length 42.9
  TOP w0.114: J1.11 52.75,46.37 60.04,46.37 v1(61.14,45.27) ; v1(63.99,21.28) 64.97,20.3 65.61,20.3 67.18,18.73 67.18,18.09 U14.70
  INT_1 w0.13: v1(63.99,21.28) 63.99,26.27 62.02,28.23 62.02,44.38 v1(61.14,45.27)
PTC1: length 40
  TOP w0.114: U14.71 67.49,18.49 67.49,19.04 65.71,20.82 v1(65.08,20.82)
  INT_1 w0.13: v1(65.08,20.82) 65.46,21.19 65.46,26.74 63.71,28.48 63.71,45.32 62.22,46.81 62.22,49.01 61.63,49.61 58.57,49.61 58.43,49.47 J1.5
PTC2: length 55.1
  TOP w0.114: v1(68.45,15.35) 69.44,16.34 69.44,17.24 U14.72
  INT_1 w0.13: J1.14 49.68,52.22 51.51,52.22 52.08,51.65 52.08,47.72 54.08,45.72 55.79,45.72 58.12,43.39 58.12,34.03 57.54,33.45 57.54,24.66 59.89,22.31 59.89,20.54 60.35,20.08 60.35,19.53 60.35,19.53 60.35,18.87 63.87,15.35 v1(68.45,15.35)
PTC3: length 50.2
  TOP w0.114: v1(62.45,23.01) 64.08,23.01 68.13,18.96 68.43,18.96 U14.73 ; J1.16 46.92,49.65 46.92,47.7 48.99,45.63 v1(59.47,45.63)
  INT_1 w0.13: v1(62.45,23.01) 60.61,24.85 60.61,33.74 59.42,34.94 59.42,42.2 60.19,42.98 60.19,44.91 v1(59.47,45.63)
PTC4: length 63.7
  TOP w0.114: U14.76 v1(71.22,22.79) ; v1(66.45,46.35) 66.45,47.03 65.31,48.18 65.31,51.43 65.92,52.04 v1(65.92,52.61) ; v1(43.89,52.61) 40.98,52.61 J2.4
  INT_1 w0.13: v1(43.89,52.61) v1(65.92,52.61) ; v1(66.45,46.35) 68.14,44.66 70.4,44.66 71.83,43.22 71.83,26.45 71.22,25.84 v1(71.22,22.79)
PTC5: length 59.8
  TOP w0.114: U14.77 v1(70.47,22.75) ; v1(65.78,46.92) 65.05,47.65 65.05,51.55 64.22,52.38 45.38,52.38 44.43,51.43 44.43,49.6 J1.15
  INT_1 w0.13: v1(70.47,22.75) 70.47,27.43 71.4,28.36 71.4,42.67 70.03,44.04 67.41,44.04 65.78,45.67 v1(65.78,46.92)
PTC6: length 63.1
  TOP w0.114: v1(65.29,37.85) 66.39,38.94 70.55,38.94 71.41,39.8 71.41,42.62 72.8,44.01 v1(72.8,44.87) C56.1 R1.2 72.8,47.6 72.8,47.6 SW2.1 ; v1(75.25,24.09) 71.11,24.09 U14.78 ; U8.11 56.32,35.43 56.52,35.24 v1(56.52,34.8) 56.52,33.83 56.9,33.45 57.46,33.45 57.84,33.83 v1(65.29,33.83)
  INT_1 w0.13: v1(65.29,33.83) v1(65.29,37.85) ; v1(75.25,24.09) 75.25,25.25 74.66,25.84 74.66,42.39 72.8,44.24 v1(72.8,44.87)
PTC7: length 51.7
  TOP w0.114: U14.79 70.63,24.33 70.63,30.08 64.5,36.21 64.5,45.14 64.73,45.38 64.73,51.33 64.01,52.05 50.15,52.05 49.49,51.39 49.49,49.49 J1.13
PTC8: length 24.8
  TOP w0.114: R79.2 62.77,43.37 63.78,42.36 63.78,36.48 70.18,30.09 70.18,24.58 U14.80
PTC9: length 36.1
  TOP w0.114: U14.81 69.74,24.85 69.74,30.04 61.76,38.02 61.76,45.89 60.98,46.66 54.99,46.66 J1.9
PTC10: length 29.5
  TOP w0.114: v1(69.29,25.1) 68.8,24.61 U14.82
  INT_1 w0.13: J4.12 69.1,8.14 69.1,10.44 72.13,13.48 72.13,16.71 69.61,19.24 69.61,24.79 v1(69.29,25.1)
PTC11: length 32.7
  TOP w0.114: U14.83 68.62,25.14 68.62,25.37 v1(69.11,25.86)
  INT_1 w0.13: J4.10 62.05,3.63 64.09,3.63 66.17,5.72 66.17,8.86 71.42,14.11 71.42,15.99 68.78,18.64 68.78,25.53 v1(69.11,25.86)
PTC12: length 18.4
  TOP w0.114: v1(67.98,25.21) U14.84
  INT_1 w0.13: J6.3 65.81,38.72 65.81,33.63 65.18,33.01 65.18,30.35 67.08,28.45 67.08,26.12 v1(67.98,25.21)
PTC13: length 26.6
  TOP w0.114: v1(55.32,34.82) 55.01,34.51 55.01,33.2 56.32,31.89 57.42,31.89 57.69,31.63 60.74,31.63 61.38,32.28 66.77,32.28 68.75,30.3 68.75,27.2 68.28,26.73 68.28,26.21 U14.85
  TOP w0.127: U8.9 v1(55.32,34.82)
PTC14: length 15.4
  TOP w0.114: U14.86 67.34,25.98 v1(67.65,26.29) ; J199.3 71.72,36.51 71.72,33.82 70.32,32.42 v1(70.32,31.12)
  INT_1 w0.13: v1(67.65,26.29) 67.65,26.74 70.32,29.41 v1(70.32,31.12)
PTC15: length 17.8
  TOP w0.114: v1(67.54,27.47) 67.23,27.16 67.23,26.58 U14.87 ; v1(70.32,33.18) 71.11,33.97 71.11,38.44 J199.4
  INT_1 w0.13: v1(70.32,33.18) 70.32,31.79 67.54,29.01 67.54,27.91 67.54,27.91 v1(67.54,27.47)
PTC16: length 33
  TOP w0.114: v1(59.71,49.13) 60.17,49.59 62.29,49.59 J1.2 ; v1(61.9,25.51) 64.04,25.51 U14.90
  INT_1 w0.13: v1(59.71,49.13) 59.71,46.59 60.57,45.73 60.57,40.51 59.84,39.78 59.84,35.55 61.04,34.36 61.04,27.41 61.9,26.55 v1(61.9,25.51)
PTC17: length 28
  TOP w0.114: v1(66,28.18) U14.91
  INT_1 w0.13: J1.4 62.17,49.64 64.32,49.64 64.79,49.18 64.79,29.84 66,28.62 v1(66,28.18)
PTC18: length 10.7
  TOP w0.114: v1(67.29,29.55) 66.98,29.24 66.35,29.24 U14.92
  INT_1 w0.13: J6.8 69.83,32.09 v1(67.29,29.55)
PTD0: length 44.4
  TOP w0.114: v1(47.67,31.42) 50.03,31.42 50.51,30.94 56.34,30.94 56.47,30.82 58.72,30.82 59.93,29.61 59.93,28.8 62.31,26.42 62.83,26.42 U14.93
  INT_1 w0.13: J2.6 36.65,49.8 37.96,48.49 37.96,46.82 41.49,43.29 43.77,43.29 46.6,40.45 46.6,32.94 47.67,31.87 v1(47.67,31.42)
PTD1: length 58.1
  TOP w0.114: v1(61.25,44.49) 59.65,46.09 49.57,46.09 v1(49.26,46.4) ; v1(62.56,26.86) U14.94
  INT_1 w0.13: v1(62.56,26.86) 61.57,27.85 61.57,44.18 v1(61.25,44.49) ; J2.12 30.88,52.67 43.08,52.67 44.48,51.27 44.48,47.5 45.59,46.4 v1(49.26,46.4)
PTD2: length 46.6
  TOP w0.114: U14.95 62.42,27.43 61.73,27.43 60.17,28.99 60.17,29.92 58.97,31.11 57.02,31.11 56.89,31.25 55.19,31.25 54.34,32.1 54.3,32.1 v1(53.99,32.41)
  INT_1 w0.13: J2.8 35.26,51.97 42.55,51.97 43.33,51.18 43.33,47.65 45.77,45.21 48.05,45.21 53.99,39.27 v1(53.99,32.41)
PTD3: length 49.5
  TOP w0.114: U14.96 62.07,27.78 61.82,27.78 60.48,29.12 60.48,30.23 59.33,31.38 57.32,31.38 57.12,31.57 55.87,31.57 v1(54.6,32.84)
  INT_1 w0.13: v1(54.6,32.84) 54.6,33.29 54.39,33.5 54.39,40.64 49.31,45.71 45.72,45.71 43.9,47.53 43.9,51.19 42.78,52.32 33.06,52.32 J2.10
PTD4: length 16.2
  TOP w0.114: v1(66.59,29.96) 63.54,29.96 U14.97
  INT_1 w0.13: v1(66.59,29.96) 66.59,31.33 68.28,33.02 68.28,38.66 J6.4
PTD5: length 12.6
  TOP w0.114: U14.98 63.31,30.43 v1(66.02,30.43)
  INT_1 w0.13: J6.5 66.19,36.56 66.19,33.36 65.52,32.69 65.52,30.94 v1(66.02,30.43)
PTD6: length 14.7
  TOP w0.114: U14.99 63.21,31.04 66.68,31.04 v1(67.29,30.43)
  INT_1 w0.13: J6.6 68.61,36.44 68.61,31.75 v1(67.29,30.43)
PTD7: length 9.3
  TOP w0.114: v1(66.04,31.73) 63.19,31.73 U14.100
  INT_1 w0.13: v1(66.04,31.73) 67.29,32.98 J6.7
PTE0: length 34.7
  TOP w0.114: v1(62.98,25.97) 62.27,25.97 59.61,28.63 59.61,29.2 U14.1 ; J15.P8 77.1,15.86 74.74,13.5 v1(69.72,13.5)
  INT_1 w0.13: v1(62.98,25.97) 62.98,19.81 63.7,19.09 63.7,17.33 64.73,16.29 68.93,16.29 69.72,15.51 v1(69.72,13.5)
PTE1: length 33.9
  TOP w0.114: v1(75.93,16.96) 76.37,16.96 J15.P7 ; v1(74.41,20.19) 73.2,20.19 73.1,20.09 73.1,19.5 73,19.4 72.86,19.4 72.76,19.5 72.76,20.09 72.66,20.19 72.52,20.19 72.42,20.09 72.42,19.5 72.32,19.4 72.17,19.4 72.07,19.5 72.07,20.09 71.97,20.19 71.83,20.19 71.73,20.09 71.73,19.5 71.63,19.4 71.49,19.4 71.39,19.5 71.39,20.09 71.29,20.19 71.15,20.19 71.04,20.09 71.04,19.5 70.94,19.4 70.8,19.4 70.7,19.5 70.7,20.09 70.6,20.19 68.35,20.19 67.41,21.13 67.41,21.86 66.87,22.4 66.3,22.4 63.9,24.8 61.9,24.8 61.34,25.35 61.34,26.41 59.25,28.5 59.25,28.84 U14.2
  INT_1 w0.13: v1(74.41,20.19) 74.41,18.47 75.62,17.27 v1(75.93,16.96)
PTE2: length 33.7
  TOP w0.114: U14.3 58.9,28.49 58.9,27.59 60.6,25.89 60.6,25.31 62.02,23.9 63.99,23.9 68.01,19.88 69.49,19.88 70.59,18.79 71.22,18.79 71.32,18.69 71.32,18.33 71.42,18.23 71.56,18.23 71.66,18.33 71.66,18.69 71.76,18.79 71.9,18.79 72,18.69 72,18.33 72.1,18.23 72.25,18.23 72.35,18.33 72.35,18.69 72.45,18.79 72.59,18.79 72.69,18.69 72.69,18.33 72.79,18.23 72.93,18.23 73.03,18.33 73.03,18.69 73.13,18.79 73.27,18.79 73.37,18.69 73.37,18.5 73.47,18.4 73.62,18.4 73.72,18.5 73.72,18.69 73.82,18.79 73.98,18.79 75.83,20.63 75.83,20.64 75.97,20.78 v1(75.97,21.24) ; v1(77.12,18.36) 77.9,18.36 78.7,19.16 J15.P5
  INT_1 w0.13: v1(75.97,21.24) 75.97,19.51 v1(77.12,18.36)
PTE3: length 34.1
  TOP w0.114: U14.4 58.55,28.14 58.55,26.57 59.33,25.79 59.33,25.79 59.59,25.53 59.59,25.53 59.61,25.51 59.61,24.84 62.18,22.28 v1(63.49,22.28) ; J15.P3 78.08,21.36 71.87,15.15 v1(70.21,15.15)
  INT_1 w0.13: v1(63.49,22.28) 63.49,21.12 64.04,20.58 64.04,17.51 64.87,16.68 69.12,16.68 70.21,15.59 v1(70.21,15.15)
PTE4: length 34.1
  TOP w0.114: J15.P2 78.48,22.46 71.92,15.9 69.93,15.9 v1(69.18,15.16) ; U14.5 58.19,27.78 58.19,26.19 v1(59.12,25.27)
  INT_1 w0.13: v1(69.18,15.16) 69.18,15.37 68.68,15.87 64.56,15.87 63.29,17.14 63.29,18.89 62.01,20.16 62.01,22.37 v1(59.12,25.27)
PTE5: length 34.5
  TOP w0.114: v1(68.32,20.85) 68.76,20.85 69.11,20.49 69.99,20.49 71.19,21.69 71.33,21.69 71.82,21.21 71.96,21.21 72.06,21.31 72.06,21.45 71.58,21.93 71.58,22.08 71.68,22.18 71.82,22.18 72.3,21.7 72.44,21.7 72.54,21.8 72.54,21.94 72.06,22.42 72.06,22.56 72.16,22.66 72.31,22.66 72.79,22.18 72.93,22.18 73.03,22.28 73.03,22.42 72.55,22.9 72.55,23.05 73.06,23.56 J15.P1 ; U14.6 57.85,27.42 57.85,25.52 62.1,21.27 63.15,21.27 v1(65.73,18.68)
  INT_1 w0.13: v1(68.32,20.85) 67.87,20.85 66.05,19.03 66.05,19 v1(65.73,18.68)
PTE6: length 33.7
  TOP w0.114: J15.G1 77.34,19.91 71.65,14.22 v1(70.52,14.22) ; U14.7 57.49,27.08 57.49,25.1 63.19,19.4 64.2,19.4 65.62,17.99 65.62,17.59 v1(65.62,17.15)
  INT_1 w0.13: v1(70.52,14.22) 70.83,14.53 70.83,15.48 69.16,17.15 66.13,17.15 66.13,17.15 66.06,17.15 66.06,17.15 v1(65.62,17.15)
PTE24: length 74.5
  TOP w0.114: U14.31 53.86,18.87 53.86,19.83 v1(55.05,21.03) ; U8.4 55.82,40.75 55.81,40.76 55.81,43.14 55.81,43.14 v1(55.81,43.77) R9.2 54.51,43.9 54.06,44.34 53.53,44.34 53.01,44.86 49.04,44.86 46.96,46.95 40.97,46.95 40.21,47.71 40.21,48.85 39.58,49.48 23.43,49.48 22.65,50.26 22.65,51.22 22.01,51.86 19.91,51.86 J2.20
  INT_1 w0.13: v1(55.05,21.03) 55.05,26.68 56.7,28.32 56.7,33.84 55.81,34.73 v1(55.81,43.77)
PTE25: length 64.7
  TOP w0.114: U14.32 54.14,18.44 54.15,18.44 54.35,18.64 v1(54.35,19.53) ; U8.6 v1(52.27,39.38) 51.66,39.38 51.02,40.03 R15.2 50.89,40.68 50.06,41.5 50.06,43.03 46.51,46.58 38.66,46.58 38.07,47.17 23.5,47.17 22.61,48.06 22.61,48.84 21.41,50.04 J2.18
  INT_1 w0.13: v1(54.35,19.53) 53.95,19.93 53.95,30.81 53.53,31.24 53.53,38.12 v1(52.27,39.38)
PTE26: length 103.2
  TOP w0.114: v1(59.38,21.21) 57.62,21.21 U14.33 ; J2.1 43.63,50.18 43.63,51.23 45.11,52.71 64.52,52.71 v1(65.09,52.14) ; v1(71.35,9.53) R73.2 70.29,8.77 68.39,10.66 67.48,10.66 66.37,11.78 v1(65.87,11.78)
  INT_1 w0.13: v1(65.87,11.78) 65.43,11.78 64.87,12.34 64.87,13.23 59.38,18.72 v1(59.38,21.21) ; v1(71.35,9.53) 71.35,11.25 72.85,12.76 72.85,30.17 74.09,31.41 74.09,41.86 70.52,45.43 68.21,45.43 65.41,48.23 65.41,51.82 v1(65.09,52.14)
REXT: length 6.6
  TOP w0.114: U13.9 29.13,26.63 26.46,23.96 C38.1 25.71,22.48 R58.1
RMII0_INT_B: length 8
  TOP w0.114: U13.18 33.27,24.43 34.26,23.43 J14.2
RMII_RXCLK: length 39.7
  TOP w0.114: U14.50 59.63,11.2 59.7,11.2 v1(59.81,11.32) ; v1(34.97,18.71) 34.47,19.22 34.47,21.18 33.32,22.32 R57.1
  INT_1 w0.13: v1(59.81,11.32) 58.76,11.32 57.52,10.08 57.36,10.08 57.2,10.24 57.03,10.24 56.92,10.12 56.92,9.96 57.08,9.8 57.08,9.64 56.97,9.53 56.81,9.53 56.65,9.69 56.48,9.69 56.37,9.57 56.37,9.41 56.53,9.25 56.53,9.09 56.1,8.66 42.29,8.66 37.02,13.93 37.02,17.73 36.03,18.71 v1(34.97,18.71)
RMII_XTALI: length 6.4
  TOP w0.114: Y2.1 25.9,26.16 C35.1 28.15,26.16 28.43,26.44 28.43,26.6 27.96,27.07 27.96,27.23 28.12,27.4 28.28,27.4 28.75,26.93 28.92,26.93 29.12,27.13 U13.8
RMII_XTALO: length 6.9
  TOP w0.114: Y2.3 23.62,28.16 24.37,27.42 25.85,27.42 26.06,27.63 C29.1 27.15,27.63 27.5,27.99 28.63,27.99 28.98,27.63 U13.7
RST_TGTMCU_B: length 150.1
  TOP w0.114: 40.73,29.81 40.4,29.81 40.02,30.19 40.02,35.72 J9.10 ; v1(15.42,44.14) 14.62,44.93 D1.C ; U14.52 61.01,11.53 60.71,11.53 57.09,7.91 49.68,7.91 48.22,6.45 35.05,6.45 34.24,5.64 34.24,3.84 J3.6 ; U3.7 R11.2 39.41,43.9 39.41,43.9 R10.2 38.91,44.43 v1(38.59,44.75) 36.79,46.56 32.49,46.56 31.04,45.1 J25.3
  INT_1 w0.13: J25.3 28.5,46.31 17.59,46.31 17.3,46.02 17.3,46.02 v1(15.42,44.14) 15.42,42.55 15.59,42.38 15.59,42.38 16.82,41.15 16.82,40.72 17.12,40.42 17.12,38.01 15.07,35.95 13.41,35.95 10.51,33.05 10.51,13.96 9.28,12.74 9.28,8.49 9.51,8.27 14,8.27 14.28,7.99 16.58,7.99 18.73,5.84 23.44,5.84 25.49,3.78 31.78,3.78 J3.6 ; J9.10 40.69,38.68 37.79,41.57 37.79,43.95 v1(38.59,44.75)
RXCLK: length 1.8
  TOP w0.114: R57.2 32.31,23.43 31.88,23.86 U13.16
RXD0: length 8.9
  TOP w0.114: RN1.4 v1(34.9,19.55) ; v1(30.28,23.38) 30.28,23.38 30.28,23.68 30.38,23.78 U13.13
  INT_1 w0.13: v1(30.28,23.38) 30.28,22.93 33.67,19.55 v1(34.9,19.55)
RXD1: length 9.2
  TOP w0.114: v1(34.94,20.41) 35.49,20.41 35.49,20.41 RN1.3 ; v1(29.68,24.33) 29.68,24.77 29.67,24.78 U13.12
  INT_1 w0.13: v1(29.68,24.33) 30.12,24.33 30.92,23.53 30.92,23.05 33.27,20.7 34.19,20.7 34.47,20.41 v1(34.94,20.41)
SDA_EXTAL: length 5.1
  TOP w0.114: U5.17 24.85,41.22 24.85,41.19 C9.1 25.86,40.84 26.17,41.15 Y1.3
SDA_JTAG_TCLK: length 9.1
  TOP w0.114: J10.4 23.73,33.9 23.34,34.3 23.34,38.99 U5.12
SDA_JTAG_TDI: length 6.8
  TOP w0.114: U5.13 23.85,39.18 23.85,36.33 J10.8
SDA_JTAG_TDO: length 8.2
  TOP w0.114: U5.14 24.38,39.36 v1(24.38,37.11)
  INT_1 w0.13: J10.6 24.38,34.52 v1(24.38,37.11)
SDA_JTAG_TMS: length 12.3
  TOP w0.114: U5.15 23.6,40.85 23.61,40.85 23.92,40.54 23.92,40.53 R21.2 25.08,38.45 24.89,38.26 v1(24.89,37.82)
  INT_1 w0.13: J10.2 23.85,32.52 23.85,37.3 24.37,37.82 v1(24.89,37.82)
SDA_LED: length 5.2
  TOP w0.114: U5.29 v1(17.97,44.36) ; D2.C v1(15.89,43.12)
  INT_1 w0.13: v1(15.89,43.12) 15.89,43.71 16.66,44.49 17.39,44.49 17.52,44.36 v1(17.97,44.36)
SDA_LED_R: length 2
  TOP w0.114: D2.A 13.06,42.25 13.05,42.25 R17.2
SDA_RST: length 17.1
  TOP w0.114: J10.10 26.73,38.03 26.73,38.67 29.61,41.55 29.61,43.15 27.69,45.07 TP5.1 26.58,44.85 R6.1 R5.2 24.11,44.85 U5.19
SDA_RST_LED: length 1.3
  TOP w0.114: R2.2 13.06,45.52 13.05,45.51 D1.A
SDA_RST_TGTMCU_B: length 11.9
  TOP w0.114: U5.21 v1(22.56,44.71)
  INT_1 w0.13: J5.2 30.75,41.47 28.11,44.11 23.15,44.11 v1(22.56,44.71)
SDA_RST_TGTMCU_J_B: length 15.1
  TOP w0.114: U3.2 42.88,43.5 43.22,43.16 43.22,42.5 R14.2 42.13,42.38 39.42,42.38 R10.1 38.03,43.77 J25.1 35.13,43.77 33.29,41.93 J5.1
SDA_RX_EN: length 2.5
  TOP w0.114: R23.2 R16.1 47.25,41.15 U7.5
SDA_SPI0_CS: length 10
  TOP w0.114: U5.23 22.8,46.37 27.42,46.37 TP1.1 29.27,45.4 R3.2
SDA_SPI0_RST_B: length 21.1
  TOP w0.114: U5.22 22.55,45.4 v1(22.78,45.4) ; v1(34.83,40.89) 35.44,40.89 35.56,40.77 TP6.1 39.31,40.77 39.71,40.37 R18.2
  INT_1 w0.13: v1(22.78,45.4) 27.99,45.4 31.63,41.76 33.96,41.76 v1(34.83,40.89)
SDA_SPI0_SCK: length 30.4
  TOP w0.114: U2.3 46.68,45.57 46.2,46.05 42.75,46.05 42.54,46.27 37.8,46.27 37.25,46.82 19.72,46.82 18.91,46.01 18.91,45.54 U5.26
SDA_SPI0_SIN: length 25.4
  TOP w0.114: v1(36.78,37.28) 37.16,36.89 U10.5 ; U5.28 18.21,44.83 18.2,44.83 v1(17.89,45.14)
  INT_1 w0.13: v1(17.89,45.14) 18.49,44.54 18.49,44.16 22.91,39.74 26.24,39.74 29.24,36.75 36.24,36.75 v1(36.78,37.28)
SDA_SPI0_SOUT: length 32.1
  TOP w0.114: v1(36.76,38.14) 37.7,38.14 38.53,37.31 42.95,37.31 44.51,35.75 U12.3 ; v1(18.66,45.02) 18.72,45.02 U5.27
  INT_1 w0.13: v1(18.66,45.02) 19.34,45.02 22.4,41.96 22.4,41.34 23.6,40.14 26.39,40.14 29.35,37.18 35.35,37.18 36.31,38.14 v1(36.76,38.14)
SDA_SWD_EN: length 2.5
  TOP w0.114: U9.6 41.2,39.86 41.2,39.87 R18.1 R19.1
SDA_SWD_EN_B: length 17.9
  TOP w0.114: U5.16 v1(24.12,41.04) ; v1(34.75,39.26) 35.19,39.26 35.29,39.36 R25.2
  INT_1 w0.13: v1(34.75,39.26) 34.75,38.64 34.24,38.14 29.52,38.14 26.63,41.04 v1(24.12,41.04)
SDA_SWD_EN_B_R: length 2.3
  TOP w0.114: U9.1 R26.2 R25.1
SDA_SWD_EN_R: length 6
  TOP w0.114: U2.5 45.4,44.73 44.83,44.16 R12.2 44.82,42.92 R13.1 44.82,41.36 43.83,40.37 R19.2
SDA_SWD_OE: length 24.1
  TOP w0.114: v1(34.26,42.25) 34.7,42.25 35.01,42.56 37.77,42.56 37.8,42.53 v1(38.24,42.53) ; R3.1 30.93,45.5 v1(30.53,45.11) ; R33.1 45.61,38.59 45.86,38.84 45.86,39.54 45.56,39.84 42.75,39.84 42.63,39.73 v1(42.63,39.7) 42.51,39.7 42.2,39.39 U9.4
  INT_1 w0.13: v1(42.63,39.7) 42.14,40.2 39.87,40.2 38.24,41.83 v1(38.24,42.53) ; v1(30.53,45.11) 31.09,45.11 32.01,44.19 32.01,42.94 32.7,42.25 v1(34.26,42.25)
SDA_SWD_OE_B: length 26.7
  TOP w0.114: v1(40.35,41.05) 39.61,41.05 39.22,41.44 34.47,41.44 34.31,41.27 v1(33.8,41.27) ; U5.20 v1(23.41,44.85) ; R28.2 v1(45.41,39.33)
  INT_1 w0.13: v1(23.41,44.85) 27.99,44.85 31.57,41.27 v1(33.8,41.27) ; v1(45.41,39.33) 44.64,39.33 43.3,40.68 40.73,40.68 v1(40.35,41.05)
SDA_SWD_OE_B_R: length 2.6
  TOP w0.114: U9.3 42.52,38.32 42.65,38.45 43.01,38.45 43.13,38.33 R27.1 44.15,38.33 44.16,38.32 R28.1
SDA_SWD_OE_R: length 5.6
  TOP w0.114: R33.2 R37.2 46.62,33.43 R39.1 45.72,33.4 45.01,34.11 U12.5
SDA_USB_CONN_DN: length 17.3
  TOP w0.114: R22.1 16.4,38.72 16.13,38.45 v1(16.13,38.18) ; v1(10.59,42.9) 10.35,42.65 8.08,42.65 7.52,43.21 U4.1 7.36,43.21 6.8,42.66 6.4,42.66 6.39,42.65 5.19,42.65 5,42.84 J26.2
  INT_1 w0.119: v1(16.13,38.18) 16.13,38.5 16.5,38.87 16.5,39.96 13.8,42.66 10.83,42.66 v1(10.59,42.9)
SDA_USB_CONN_DP: length 16.7
  TOP w0.114: R20.1 16.21,38.91 16.08,38.78 v1(15.53,38.78) ; v1(10.59,42.04) 10.26,42.38 8.08,42.38 7.53,41.83 U6.1 7.36,41.83 6.81,42.38 5.19,42.38 5,42.19 J26.3
  INT_1 w0.119: v1(10.59,42.04) 10.92,42.37 13.68,42.37 16.21,39.84 16.21,38.99 16,38.78 v1(15.53,38.78)
SDA_USB_DN: length 1.8
  TOP w0.114: U5.4 18.24,40.39 18.08,40.39 17.63,39.94 R22.2
SDA_USB_DP: length 1.8
  TOP w0.114: U5.3 17.89,40.75 17.89,40.59 17.44,40.14 R20.2
SDA_USB_P5V_SENSE: length 2.9
  TOP w0.114: U5.30 17.42,44.19 17.42,44.47 R8.2 16.1,44.82 R7.1
SDA_USBSHIELD: length 28.6
  TOP w0.762: L2.1 4.64,37.77 ; L2.1 5.14,37.17 ; L2.1 4.15,37.17 ; L2.1 4.64,36.58 ; 1.5,36.51 J26.S4 2.65,38.01 ; J26.S1 4.5,45.14 ; 1.5,47.86 J26.S3 2.65,46.36 ; 4.5,39.24 J26.S2
  BOTTOM w0.508: J26.S4 2.65,38.75 ; J26.S4 1.5,38.75 ; J26.S4 2.65,38.01 ; J26.S4 2.65,37.28 ; J26.S4 1.5,37.28 ; 3.61,44.41 J26.S1 ; J26.S1 3.61,43.69 ; J26.S1 5.39,44.41 ; J26.S1 4.5,45.14 ; J26.S1 4.5,43.69 ; 4.5,39.24 J26.S2 ; J26.S2 3.61,40.69 ; J26.S2 3.61,39.24 ; J26.S2 3.61,39.96 ; J26.S2 4.5,40.69 ; J26.S3 1.5,47.1 ; J26.S3 2.65,46.36 ; J26.S3 1.5,45.63 ; J26.S3 2.65,47.1 ; J26.S3 2.65,45.63
SDA_VOUT33: length 9.4
  TOP w0.254: U5.5 18.21,39.65 18.21,39.14 16.36,37.28 15.11,37.28 14.43,37.96 C11.1 12.64,37.96 J7.2
SDA_XTAL: length 5
  TOP w0.114: Y1.1 26.02,43.55 25.71,43.85 C6.1 23.82,43.85 23.02,43.05
SHIELD_K64USB: length 28.4
  TOP w0.762: 4.54,8.4 J22.S2 ; 1.54,5.68 J22.S4 2.68,7.17 ; J22.S1 4.54,14.3 ; 2.68,15.52 J22.S3 1.54,17.02 ; 4.44,15.88 L4.1 ; L4.1 4.44,17.07 ; L4.1 3.94,16.47
  BOTTOM w0.508: J22.S3 1.54,16.26 ; J22.S3 2.68,16.26 ; J22.S3 2.68,15.52 ; J22.S3 2.68,14.79 ; J22.S3 1.54,14.79 ; 3.65,13.58 J22.S1 ; J22.S1 4.54,14.3 ; J22.S1 3.65,14.3 ; J22.S1 3.65,12.85 ; J22.S1 4.54,12.85 ; 3.65,9.85 J22.S2 ; J22.S2 3.65,8.4 ; J22.S2 4.54,8.4 ; J22.S2 4.54,9.85 ; J22.S2 3.65,9.12 ; J22.S4 2.68,7.91 ; J22.S4 2.68,6.44 ; J22.S4 1.54,7.91 ; J22.S4 2.68,7.17 ; J22.S4 1.54,6.44
SW1_RST_B: length 32.3
  TOP w0.114: v1(31.88,45.24) 32.67,46.03 32.99,46.03 C2.1 33.57,44.76 J25.2 ; SW1.2 8.02,48.69 8.81,47.91 v1(9.25,47.91)
  INT_1 w0.13: v1(9.25,47.91) 12.19,44.96 15.58,44.96 17.31,46.69 29.26,46.69 30.22,45.72 31.4,45.72 v1(31.88,45.24)
SWD_CLK_TGTMCU: length 15.1
  TOP w0.114: J11.2 46.37,31.66 46.94,32.24 49.46,32.24 50.04,32.81 J8.2
  INT_1 w0.13: J9.4 40.01,31.9 40.01,30.97 40.6,30.37 45.4,30.37 45.42,30.36 J11.2
SWD_CLK_TGTMCU_BUF: length 15.9
  TOP w0.114: U2.4 v1(45.08,45.23)
  INT_1 w0.13: v1(45.08,45.23) 46.16,44.15 47.17,44.15 48.21,43.11 48.21,43.1 49.57,41.74 49.57,39.75 52.58,36.75 J8.1
SWD_DIO_TGTMCU_BUF: length 16.5
  TOP w0.114: J12.1 44.51,29.05 U12.4 44.07,34.55 42.84,35.77 42.84,36.51 42.29,37.07 40.38,37.07 39.1,35.79 U10.2
TC_EXTAL_TP: length 2.3
  TOP w0.114: TP9.1 v1(22.05,38.52) 21.64,38.93 21.64,39.27 U5.10
TC_SDA_USB_ID_TP: length 4.1
  TOP w0.114: J26.4 6,41.54 v1(6.44,41.54) 6.44,40.79 6.81,40.42 TP7.1
TC_USB_ID_TP: length 5.1
  TOP w0.114: J22.4 v1(6.1,10.7) 6.66,10.14 TP15.1 6.86,8.83 R72.1
TC_XTAL_TP: length 2.7
  TOP w0.114: U5.9 21.37,38.83 v1(21.37,37.66) TP10.1
TP_2102_A: length 2.2
  TOP w0.114: U3.3 43.17,43.9 43.78,44.51 TP3.1
TP_2102_B: length 2.4
  TOP w0.114: TP2.1 40.47,44.3 U3.6
TRACE_SWO: length 12.8
  TOP w0.114: v1(47,31.62) 47.31,31.93 51.04,31.93 51.39,31.58 R80.1
  INT_1 w0.13: J9.6 41.39,33.13 45.49,33.13 v1(47,31.62)
UART1_RX_TGTMCU_BUF: length 1.2
  TOP w0.114: U7.4 46.67,40.31 46.68,40.31 R24.1
UART1_RX_TGTMCU_R: length 35
  TOP w0.114: v1(46.13,39.96) 45.91,40.17 U7.3 ; v1(44.84,37.34) 44.4,37.34 44.18,37.56 38.94,37.56 37.68,38.82 36.48,38.82 36.48,38.82 v1(36.04,38.82) ; U5.25 v1(19.43,45.73)
  INT_1 w0.13: v1(44.84,37.34) 46.13,38.63 v1(46.13,39.96) ; v1(36.04,38.82) 34.87,37.64 29.48,37.64 26.59,40.54 23.97,40.54 22.84,41.68 22.84,42.32 v1(19.43,45.73)
UART1_TX_TGTMCU_BUF: length 1.4
  TOP w0.114: R38.1 38.36,34.42 38.36,34.42 U10.1
UART1_TX_TGTMCU_R: length 22
  TOP w0.114: U5.24 20.63,45.44 20.63,45.68 v1(20.62,45.7) ; U10.6 36.75,35.79 36.24,36.3 36.24,37.29 34.94,38.6 v1(33.41,38.6)
  INT_1 w0.13: v1(33.41,38.6) 29.79,38.6 26.9,41.49 24.58,41.49 24.18,41.89 24.17,41.89 23.91,42.15 23.91,42.4 v1(20.62,45.7)
USB_CONN_DN: length 59.4
  TOP w0.114: J22.2 5.04,12 5.23,11.81 6.64,11.81 7.25,12.41 U16.1 7.38,12.41 7.97,11.83 10.9,11.83 v1(11.22,12.15) ; R49.1 52.32,28.91 52.32,29.56 52.15,29.73 v1(51.74,29.73)
  INT_1 w0.119: v1(11.22,12.15) 11.49,11.88 15.24,11.88 28.45,25.09 32.76,25.09 33.58,25.91 37.84,25.91 38.05,25.7 48.77,25.7 50.25,27.18 50.25,27.35 50.18,27.42 50.18,27.59 50.35,27.76 50.52,27.76 50.59,27.69 50.76,27.69 50.93,27.86 50.93,28.03 50.86,28.09 50.86,28.26 51.03,28.43 51.19,28.43 51.26,28.36 51.43,28.36 52.29,29.22 52.29,29.58 52.14,29.73 v1(51.74,29.73)
USB_CONN_DP: length 59.4
  TOP w0.114: J22.3 5.04,11.35 5.23,11.54 6.63,11.54 7.23,10.94 U18.1 7.36,10.94 7.97,11.55 10.96,11.55 v1(11.22,11.29) ; v1(52.35,30.34) 52.35,29.92 52.51,29.75 53.13,29.75 R46.1
  INT_1 w0.119: v1(52.35,30.34) 52.35,29.94 52.58,29.7 52.58,29.09 48.89,25.41 37.93,25.41 37.72,25.61 33.71,25.61 32.88,24.79 28.57,24.79 15.37,11.59 11.52,11.59 v1(11.22,11.29)
V_TGTMCU: length 35.9
  TOP w0.127: v1(41.22,42.88) R11.1
  TOP w0.203: U3.8 41.33,42.99 v1(41.22,42.88)
  TOP w0.254: v1(45.97,33.99) 45.51,34.45 U12.6 ; U7.6 v1(46.67,42.23) C7.1 45.98,43.5 45.92,43.56 U2.6 ; U10.8 37.76,34.56 v1(37.7,34.5)
  TOP w0.635: v1(35.7,32.45) 36.06,32.09 SH1.1 37.58,31.53 C23.1 v1(38.48,31.54) ; v1(14.83,45.93) 14.58,46.19 R2.1
  BOTTOM w0.381: 39.21,46.41 39.03,46.41 38.6,46.84 25.04,46.84 24.75,47.13 18.14,47.13 17.72,46.71 16.86,46.71 15.89,45.75 15.02,45.75 v1(14.83,45.93)
VOUT33_K64: length 6.6
  TOP w0.127: U14.12 54.02,27.01 52.9,27.01 51.56,28.35 TP12.1 50.3,28.35 C59.1
VREFH: length 7.3
  TOP w0.254: R52.2 48.37,23.11 48.38,23.12 R54.2 50.13,23.12 U14.23
  TOP w0.635: D4.C 45.97,22.15 45.96,22.16 R53.1 45.97,23.11 R52.2
VREGIN_K64: length 17.3
  TOP w0.305: U14.13 53.78,26.54 v1(53.42,26.54) 52.97,26.54 C33.1
  BOTTOM w0.635: v1(53.42,26.54) 52.93,27.03 50.1,27.03 48.06,24.99 48.05,24.99 47.35,24.29 47.35,22.67 44.5,19.83 J16.1
VTRG_EN: length 8.8
  TOP w0.114: R29.2 28.99,38.18 29.36,37.82 R30.1 30.71,37.24 30.98,36.96 33.87,36.96 R34.2 34.58,36.24 U11.3
VTRG_FAULT_B: length 18
  TOP w0.114: U11.4 29.83,36.24 29.83,36.24 R35.2 v1(28.4,36.24) ; U5.32 v1(16.93,43.27)
  INT_1 w0.13: v1(28.4,36.24) 27.62,36.24 25.51,38.35 23.97,38.35 23.61,37.99 21.95,37.99 21.17,38.76 21.17,38.94 17.24,42.86 17.24,42.96 v1(16.93,43.27)
XTAL32_RTC: length 2.5
  TOP w0.114: U14.28 50.2,17.33 49.53,17.33 R62.1
XTAL_32.768KHZ: length 5.1
  TOP w0.114: R62.2 48.04,15.83 48.04,15.83 R65.2 47.41,15.21 46.44,15.21 C44.1 45.56,14.33 45.56,14 Y3.1
XTAL_K64_MAIN: length 2
  TOP w0.114: R74.1 62.35,9.48 62.35,9.48 U14.51
N20614543: length 5.6
  TOP w0.114: U13.24 35.25,27.63 35.95,26.93 C34.1 36.83,26.93 36.84,26.94 R50.2 37.97,26.94 37.98,26.93 D3.3
N20654921: length 6
  TOP w0.114: RN1.2 34.99,21.21 34.32,21.89 34.32,22.73 33.38,23.68 32.59,23.68 32.38,23.89 U13.17
N20657567: length 21.8
  TOP w0.114: R36.2 11.24,35.28 10.49,36.03 6.07,36.03 3.17,33.13 J13.14

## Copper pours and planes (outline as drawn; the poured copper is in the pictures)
GND on TOP: 24.02,42.72 24.02,42.73 24.59,43.3 25.75,43.3 25.96,43.09 28.99,43.09 29.4,42.68 29.4,41.82 29.06,41.48 24.9,41.48 23.97,42.41 23.97,42.67
GND on TOP: 23.15,24.68 22.32,25.51 22.32,28.82 22.84,29.34 28.57,29.34 28.97,28.94 28.97,26.99 26.66,24.68 ; 1 cut-out
GND on TOP: 49.24,26.59 50.11,26.59 50.88,27.36 51.29,27.36 51.74,26.9 51.74,25.82 50.78,24.86 49.7,24.86 49.23,25.33 49.23,26.58
